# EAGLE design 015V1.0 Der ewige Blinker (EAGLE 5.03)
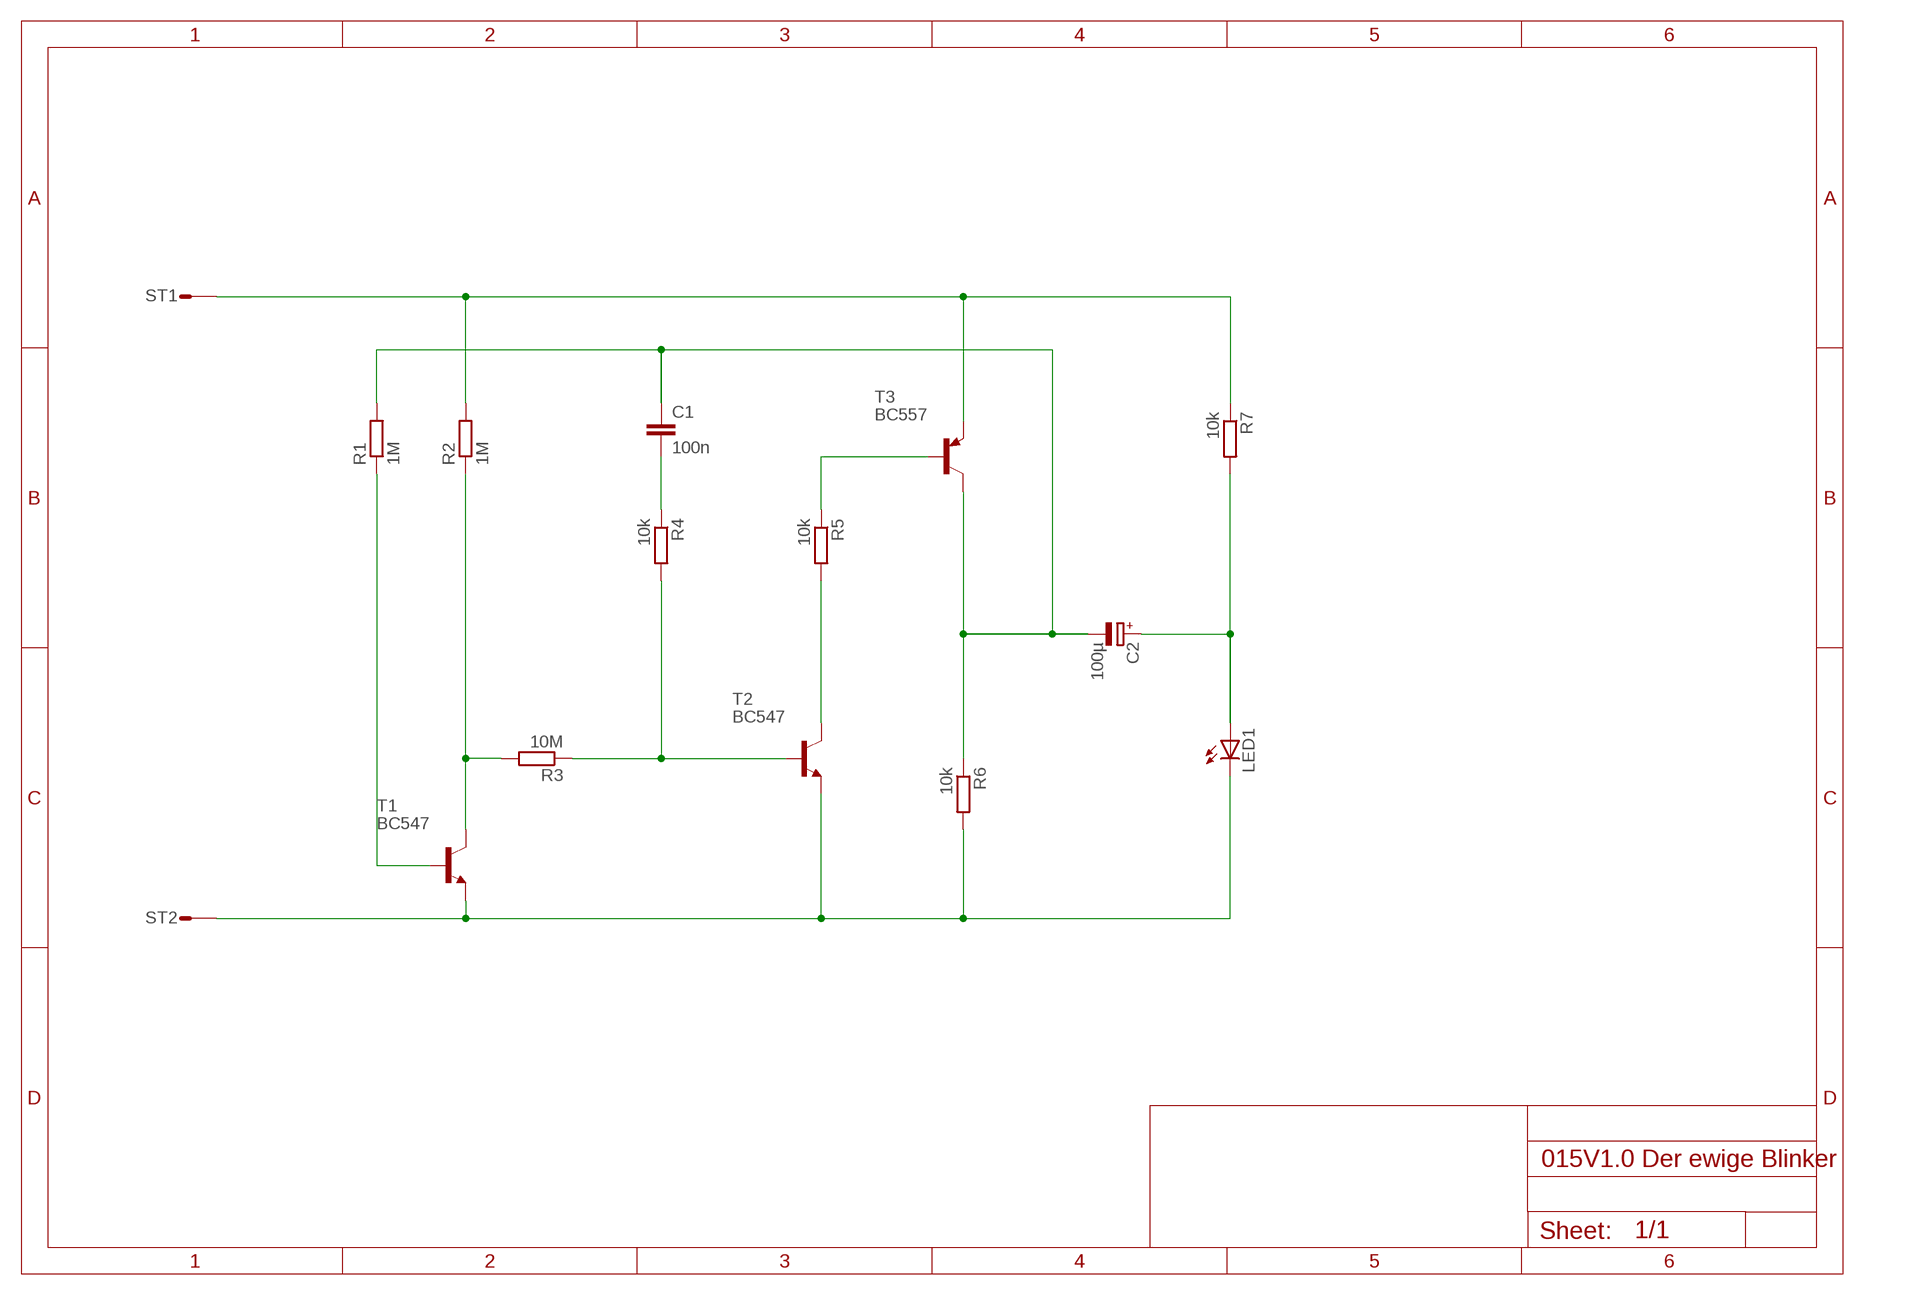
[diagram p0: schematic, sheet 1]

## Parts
C1  100n  C-EU050-024X044  [C050-024X044]
C2  100µ  CPOL-EUE3.5-8  [E3,5-8]
LED1  LED5MM  [LED5MM]
R1  1M  R-EU_0207/7  [0207/7]
R2  1M  R-EU_0207/7  [0207/7]
R3  10M  R-EU_0207/7  [0207/7]
R4  10k  R-EU_0207/7  [0207/7]
R5  10k  R-EU_0207/7  [0207/7]
R6  10k  R-EU_0207/7  [0207/7]
R7  10k  R-EU_0207/7  [0207/7]
ST1  ST2,8  [ST2,8]
ST2  ST2,8  [ST2,8]
T1  BC547  -NPN-TO92L  [TO92L]
T2  BC547  -NPN-TO92L  [TO92L]
T3  BC557  -PNP-TO92L  [TO92L]

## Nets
GND: LED1.K(C) R6.2 ST2.1(ST) T1.1(E) T2.1(E)
N$1: R2.2 R7.1 ST1.1(ST) T3.1(E)
N$2: R1.1 T1.2(B)
N$3: R2.1 R3.2 T1.3(C)
N$4: R3.1 R4.2 T2.2(B)
N$5: C1.2 R4.1
N$6: R5.2 T2.3(C)
N$7: R5.1 T3.2(B)
N$9: C2.+ LED1.A R7.2
N$10: C1.1 C2.- R1.2 R6.1 T3.3(C)

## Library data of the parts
C1 = rcl:C-EU: CAPACITOR, European symbol
C2 = rcl:CPOL-EU: POLARIZED CAPACITOR, European symbol
LED1 = led:LED: LED
R1-R7 = rcl:R-EU_: RESISTOR, European symbol
ST1 ST2 = con-rib:ST2,8: RIBBON CABLE CONNECTOR
T1 T2 = transistor-neu-to92:*-NPN-: NPN Transistror
T3 = transistor-neu-to92:*-PNP-: PNP Transistror

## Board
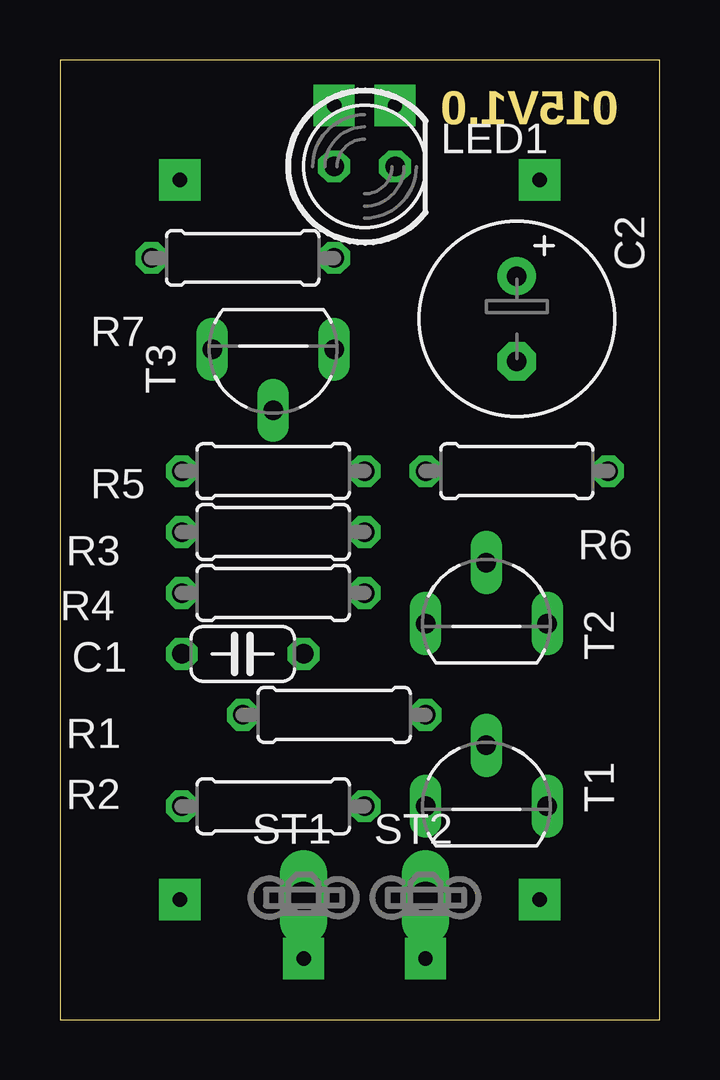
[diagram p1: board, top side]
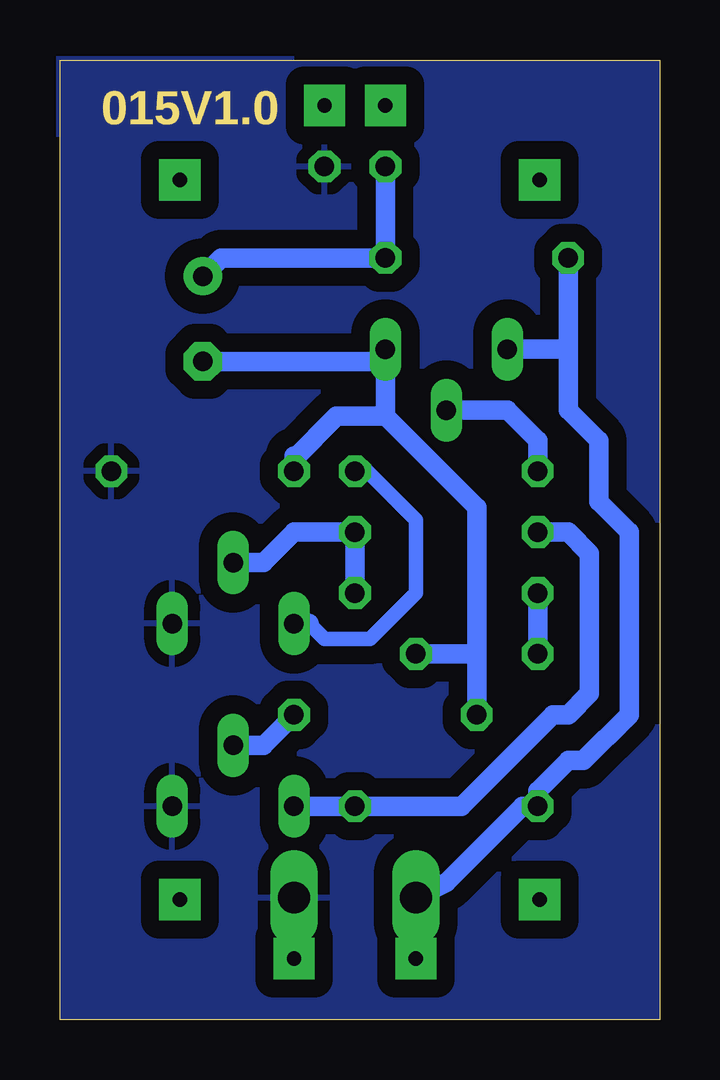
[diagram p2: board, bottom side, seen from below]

Size 25 x 40 mm. Coordinates in mm from the lower left corner, seen from the top.
Outline: 0,0 25,0 25,40 0,40 0,0
Copper layers (1*16): Top 0.035mm / dielectric 1.5mm / Bottom 0.035mm
Design rules "default *": minimum track width 10mil, minimum drill 24mil, track to track 30mil, track to pad 30mil, pad to pad 8mil, via to via 20mil, smd to smd 8mil, copper to edge 1mil, drill to drill 8mil, minimum pad ring 10mil, minimum via ring 22mil, stop-mask expansion 4mil, vias tented up to drill 0mil, thermal gap 20mil

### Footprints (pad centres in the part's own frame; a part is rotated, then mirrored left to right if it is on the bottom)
C050-024X044 = drill 0.813 octagon: 1 -2.54,0; 2 2.54,0
E3,5-8 = drill 0.813 pad 1.6 round: + -1.778,0 | drill 0.813 pad 1.6 octagon: - 1.778,0
LED5MM = drill 0.813 octagon: A -1.27,0; K 1.27,0
0207/7 = drill 0.813 octagon: 1 -3.81,0; 2 3.81,0
ST2,8 = drill 1.321 long: 1 0,0
TO92L = drill 0.813 long: 1 0,-2.54; 2 2.54,0; 3 0,2.54

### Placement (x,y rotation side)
C1  7.62,15.24 180 top
C2  19.05,29.21 270 top
LED1  12.7,35.56 0 top
R1  11.43,12.7 180 top
R2  8.89,8.89 180 top
R3  8.89,20.32 180 top
R4  8.89,17.78 0 top
R5  8.89,22.86 0 top
R6  19.05,22.86 0 top
R7  7.62,31.75 0 top
ST1  10.16,5.08 0 top
ST2  15.24,5.08 0 top
T1  17.78,8.89 90 top
T2  17.78,16.51 90 top
T3  8.89,27.94 270 top

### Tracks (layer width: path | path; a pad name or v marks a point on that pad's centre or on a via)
GND
  pour Bottom: 0,0 25.4,0 25.15,36.83 15.75,36.83 15.75,40.64 0,40.64
  pour Bottom (no thermals): 15.24,40.13 25.15,40.13 25.15,36.83 15.24,36.83
N$1
  Bottom 0.813: 3.81,27.94 T3.1 | 3.81,27.94 R7.1 | ST1.1 8.89,5.71 5.71,8.89 R2.2 5.08,9.53 3.81,10.79 3.17,10.79 1.27,12.7 1.27,20.32 2.54,21.59 2.54,24.13 3.81,25.4 3.81,27.94
N$2
  Bottom 0.813: T1.2 16.51,11.43 R1.1
N$3
  Bottom 0.813: T1.3 R2.1 8.26,8.89 4.45,12.7 3.81,12.7 2.92,13.59 2.92,19.43 3.81,20.32 R3.2
N$4
  Bottom 0.813: T2.2 16.51,19.05 15.24,20.32 R3.1 R4.2
N$5
  Bottom 0.813: C1.2 R4.1
N$6
  Bottom 0.61: 14.61,16.51 13.97,15.88 12.06,15.88 10.16,17.78 10.16,20.83 12.19,22.86 R5.2
  Bottom 0.813: 14.61,16.51 T2.3
N$7
  Bottom 0.813: R5.1 5.08,24.13 6.35,25.4 T3.2
N$8  (via drill 0.6)
  other vias: 5,35
N$9
  Bottom 0.813: LED1.A R7.2 18.29,31.75 C2.+
N$10
  Bottom 0.813: 15.24,23.37 R6.1 | 15.24,23.37 15.24,23.5 | 11.43,25.15 T3.3 11.94,27.43 C2.- | 11.43,25.15 13.46,25.15 15.24,23.37 | R1.2 7.62,15.24 | 7.62,15.24 7.62,21.34 11.43,25.15 | 7.62,15.24 C1.1
N$11  (via drill 0.6)
  other vias: 20,35
N$12  (via drill 0.6)
  other vias: 20,5
N$13  (via drill 0.6)
  other vias: 5,5
N$14  (via drill 0.6)
  other vias: 15.24,2.54
N$15  (via drill 0.6)
  other vias: 10.16,2.54
N$16  (via drill 0.6)
  other vias: 11.43,38.1
N$17  (via drill 0.6)
  other vias: 13.97,38.1

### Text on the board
Dimension: 015V1.0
